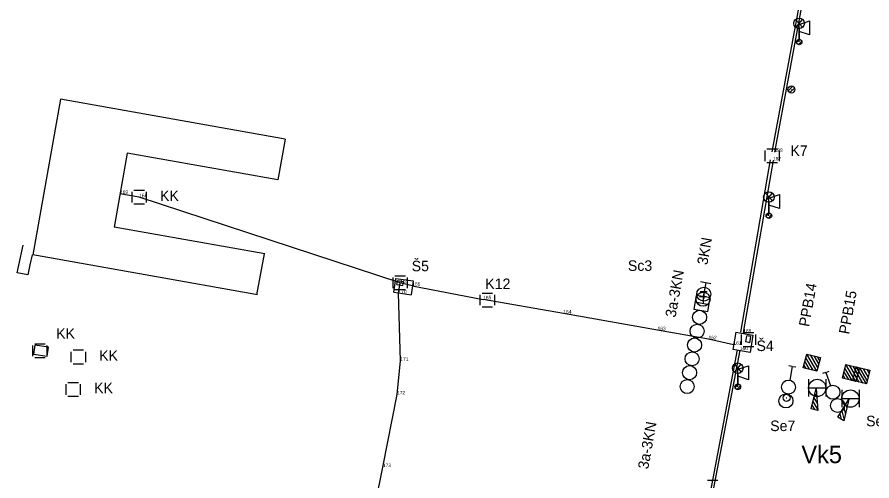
# Model space of a CAD drawing. Extents: x -866945 to -849632, y -1066564 to -1049105.
# Drawn here: x -866577.7 to -866456.1, y -1049962.8 to -1049896.8 of the extents above; entities that cross this region are included whole.
import ezdxf

# ---------------------------------------------------------------- set-up
doc = ezdxf.new("R2010")
doc.units = 0
for name, color, linetype in [('Vrstva 16', 7, 'Continuous'), ('Vrstva 2', 7, 'Continuous'), ('Vrstva 23', 7, 'Continuous'), ('Vrstva 25', 7, 'Continuous'), ('Vrstva 3', 7, 'Continuous'), ('Vrstva 31', 7, 'Continuous'), ('Vrstva 32', 7, 'Continuous'), ('Vrstva 33', 7, 'Continuous'), ('Vrstva 35', 7, 'Continuous'), ('Vrstva 36', 7, 'Continuous'), ('Vrstva 51', 7, 'Continuous'), ('Vrstva 52', 7, 'Continuous'), ('Vrstva 6', 7, 'Continuous'), ('Vrstva 7', 7, 'Continuous')]:
    doc.layers.add(name, color=color, linetype=linetype)

msp = doc.modelspace()

# ---------------------------------------------------------------- linework, layer by layer
at = {"layer": 'Vrstva 16'}
for p, q in [((-866524.06, -1049935.92), (-866523.79, -1049933.97)), ((-866523.79, -1049933.97), (-866521.33, -1049934.31)), ((-866523.66, -1049934.83), (-866523.57, -1049934.24)), ((-866523.57, -1049934.24), (-866522.69, -1049934.37)), ((-866523.66, -1049934.83), (-866522.78, -1049934.97)), ((-866522.78, -1049934.97), (-866522.69, -1049934.37)), ((-866521.33, -1049934.31), (-866521.6, -1049936.28)), ((-866524.06, -1049935.91), (-866524.06, -1049935.92)), ((-866524.06, -1049935.91), (-866521.6, -1049936.28)), ((-866475.44, -1049941.61), (-866475.86, -1049944.06)), ((-866475.44, -1049941.61), (-866472.99, -1049942.02)), ((-866474.02, -1049943), (-866473.87, -1049942.12)), ((-866473.28, -1049942.23), (-866473.87, -1049942.12)), ((-866473.43, -1049943.11), (-866473.28, -1049942.23)), ((-866472.99, -1049942.02), (-866473.4, -1049944.49)), ((-866473.43, -1049943.11), (-866474.02, -1049943)), ((-866473.4, -1049944.49), (-866475.86, -1049944.06))]:
    msp.add_line(p, q, dxfattribs=at)
at = {"layer": 'Vrstva 23'}
for points in [[(-866571.49, -1049908.45), (-866575.43, -1049930.6)], [(-866539.52, -1049914.14), (-866571.49, -1049908.45)], [(-866539.52, -1049914.14), (-866540.55, -1049919.93)], [(-866561.99, -1049916.12), (-866563.86, -1049926.65)], [(-866540.55, -1049919.93), (-866561.99, -1049916.12)], [(-866542.42, -1049930.46), (-866563.86, -1049926.65)], [(-866543.46, -1049936.29), (-866575.43, -1049930.6)], [(-866542.5, -1049930.45), (-866543.58, -1049936.27)]]:
    msp.add_lwpolyline(points, dxfattribs=at)
at = {"layer": 'Vrstva 25'}
for p, q in [((-866466.92, -1049897.09), (-866465.93, -1049898.21)), ((-866466.91, -1049898.22), (-866465.93, -1049897.1)), ((-866466.43, -1049898.4), (-866466.43, -1049899.9)), ((-866466.82, -1049900.38), (-866466.35, -1049899.91)), ((-866466.55, -1049900.68), (-866466.05, -1049900.18)), ((-866471.22, -1049921.81), (-866470.23, -1049922.93)), ((-866471.21, -1049922.94), (-866470.22, -1049921.82)), ((-866470.73, -1049923.12), (-866470.73, -1049924.62)), ((-866471.12, -1049925.1), (-866470.65, -1049924.63)), ((-866470.85, -1049925.4), (-866470.35, -1049924.9)), ((-866475.64, -1049946.17), (-866474.65, -1049947.28)), ((-866475.63, -1049947.3), (-866474.65, -1049946.18)), ((-866475.15, -1049947.48), (-866475.15, -1049948.98)), ((-866475.54, -1049949.46), (-866475.07, -1049948.99)), ((-866475.27, -1049949.76), (-866474.77, -1049949.26))]:
    msp.add_line(p, q, dxfattribs=at)
for centre, radius in [((-866466.43, -1049897.65), 0.749), ((-866466.43, -1049900.3), 0.4), ((-866466.43, -1049900.3), 0.4), ((-866470.73, -1049922.37), 0.749), ((-866470.73, -1049925.02), 0.4), ((-866470.73, -1049925.02), 0.4), ((-866475.15, -1049946.73), 0.749), ((-866475.15, -1049949.38), 0.4), ((-866475.15, -1049949.38), 0.4)]:
    msp.add_circle(centre, radius, dxfattribs=at)
at = {"layer": 'Vrstva 3'}
for p, q in [((-866480.59, -1049936.51), (-866479.59, -1049936.51)), ((-866480.49, -1049935.79), (-866479.49, -1049935.79)), ((-866480.09, -1049936.51), (-866480.09, -1049937.51)), ((-866479.99, -1049935.79), (-866479.99, -1049936.79)), ((-866464.42, -1049947.03), (-866465.47, -1049945.24)), ((-866463.9, -1049947.16), (-866465.34, -1049944.72)), ((-866463.77, -1049946.65), (-866464.83, -1049944.85)), ((-866463.64, -1049946.13), (-866464.31, -1049944.99)), ((-866463.51, -1049945.62), (-866463.8, -1049945.12)), ((-866465.44, -1049946.76), (-866465.74, -1049946.26)), ((-866464.93, -1049946.89), (-866465.61, -1049945.75)), ((-866458.34, -1049948.63), (-866459.78, -1049946.19)), ((-866458.21, -1049948.12), (-866459.27, -1049946.32)), ((-866459.37, -1049948.36), (-866460.05, -1049947.22)), ((-866458.86, -1049948.5), (-866459.91, -1049946.71)), ((-866458.08, -1049947.6), (-866458.75, -1049946.46)), ((-866457.89, -1049948.7), (-866458.57, -1049947.56)), ((-866457.38, -1049948.84), (-866458.43, -1049947.05)), ((-866456.86, -1049948.97), (-866458.3, -1049946.53)), ((-866457.95, -1049947.09), (-866458.24, -1049946.59)), ((-866456.73, -1049948.46), (-866457.79, -1049946.66)), ((-866456.6, -1049947.94), (-866457.27, -1049946.8)), ((-866456.47, -1049947.43), (-866456.76, -1049946.93)), ((-866465.09, -1049948.31), (-866465.09, -1049950.77)), ((-866462.63, -1049948.31), (-866462.63, -1049950.77)), ((-866459.88, -1049948.23), (-866460.18, -1049947.73)), ((-866458.4, -1049948.57), (-866458.7, -1049948.07)), ((-866465.09, -1049949.54), (-866462.63, -1049949.54)), ((-866464.06, -1049949.93), (-866463.94, -1049950.14)), ((-866460.36, -1049949.82), (-866460.36, -1049952.28)), ((-866457.9, -1049949.82), (-866457.9, -1049952.28)), ((-866464.33, -1049950.95), (-866463.83, -1049951.81)), ((-866464.2, -1049950.44), (-866463.88, -1049950.97)), ((-866460.36, -1049951.05), (-866457.9, -1049951.05)), ((-866464.73, -1049952.49), (-866464.72, -1049952.51)), ((-866464.6, -1049951.98), (-866464.21, -1049952.64)), ((-866464.46, -1049951.47), (-866463.77, -1049952.64)), ((-866460.08, -1049952.34), (-866459.85, -1049953.3)), ((-866459.8, -1049951.89), (-866459.66, -1049952.49)), ((-866459.52, -1049951.44), (-866459.46, -1049951.67)), ((-866460.91, -1049953.69), (-866460.91, -1049953.71)), ((-866460.64, -1049953.24), (-866460.46, -1049953.99)), ((-866460.36, -1049952.79), (-866460.04, -1049954.12))]:
    msp.add_line(p, q, dxfattribs=at)
for points in [[(-866465.84, -1049946.66), (-866465.34, -1049944.72), (-866463.4, -1049945.22), (-866463.9, -1049947.16)], [(-866465.84, -1049946.66), (-866465.34, -1049944.72), (-866463.4, -1049945.22), (-866463.9, -1049947.16)], [(-866460.28, -1049948.13), (-866459.78, -1049946.19), (-866457.84, -1049946.69), (-866458.34, -1049948.63)], [(-866460.28, -1049948.13), (-866459.78, -1049946.19), (-866457.84, -1049946.69), (-866458.34, -1049948.63)], [(-866458.8, -1049948.47), (-866458.3, -1049946.53), (-866456.36, -1049947.03), (-866456.86, -1049948.97)], [(-866458.8, -1049948.47), (-866458.3, -1049946.53), (-866456.36, -1049947.03), (-866456.86, -1049948.97)]]:
    msp.add_lwpolyline(points, close=True, dxfattribs=at)
for points in [[(-866465.84, -1049946.66), (-866465.34, -1049944.72), (-866463.4, -1049945.22), (-866463.9, -1049947.16), (-866465.84, -1049946.66)], [(-866465.84, -1049946.66), (-866465.34, -1049944.72), (-866463.4, -1049945.22), (-866463.9, -1049947.16), (-866465.84, -1049946.66)], [(-866460.28, -1049948.13), (-866459.78, -1049946.19), (-866457.84, -1049946.69), (-866458.34, -1049948.63), (-866460.28, -1049948.13)], [(-866460.28, -1049948.13), (-866459.78, -1049946.19), (-866457.84, -1049946.69), (-866458.34, -1049948.63), (-866460.28, -1049948.13)], [(-866458.8, -1049948.47), (-866458.3, -1049946.53), (-866456.36, -1049947.03), (-866456.86, -1049948.97), (-866458.8, -1049948.47)], [(-866458.8, -1049948.47), (-866458.3, -1049946.53), (-866456.36, -1049947.03), (-866456.86, -1049948.97), (-866458.8, -1049948.47)], [(-866463.98, -1049949.6), (-866463.77, -1049952.76), (-866464.73, -1049952.5), (-866463.98, -1049949.6)], [(-866463.98, -1049949.6), (-866463.77, -1049952.76), (-866464.73, -1049952.5), (-866463.98, -1049949.6)], [(-866459.34, -1049951.15), (-866460.07, -1049954.23), (-866460.92, -1049953.7), (-866459.34, -1049951.15)], [(-866459.34, -1049951.15), (-866460.07, -1049954.23), (-866460.92, -1049953.7), (-866459.34, -1049951.15)]]:
    msp.add_lwpolyline(points, dxfattribs=at)
for centre, radius in [((-866479.99, -1049936.19), 1), ((-866480.09, -1049936.91), 1), ((-866463.86, -1049949.54), 1.23), ((-866459.13, -1049951.05), 1.23)]:
    msp.add_circle(centre, radius, dxfattribs=at)
at = {"layer": 'Vrstva 32'}
msp.add_line((-866475.76, -1049943.41), (-866479.31, -1049942.62), dxfattribs=at)
for points in [[(-866467.53, -1049907.06), (-866467.46, -1049907.09)], [(-866521.45, -1049935), (-866523.16, -1049934.59), (-866560.29, -1049922.4), (-866563.02, -1049921.91)], [(-866546.33, -1050037.54), (-866545.05, -1050037.8), (-866543.62, -1050037.78), (-866542.32, -1050036.4), (-866541.04, -1050031.45), (-866538.21, -1050019.09), (-866535.65, -1050003.43), (-866534.99, -1050000.66), (-866533.44, -1049996.5), (-866532.34, -1049992.41), (-866530.9, -1049985.87), (-866527.79, -1049971.38), (-866525.62, -1049960.81), (-866523.61, -1049950.46), (-866523.14, -1049945.69), (-866523.41, -1049936.07), (-866523.16, -1049934.59)], [(-866479.31, -1049942.62), (-866486.56, -1049941.33), (-866499.96, -1049938.96), (-866511.37, -1049936.93)]]:
    msp.add_lwpolyline(points, dxfattribs=at)
at = {"layer": 'Vrstva 33'}
for p, q in [((-866466.43, -1049900.3), (-866466.43, -1049897.5)), ((-866470.73, -1049925.02), (-866470.73, -1049922.22)), ((-866475.15, -1049949.38), (-866475.15, -1049946.58))]:
    msp.add_line(p, q, dxfattribs=at)
for points in [[(-866466.43, -1049897.8), (-866464.93, -1049897.3), (-866464.93, -1049899.3), (-866466.43, -1049898.8)], [(-866470.73, -1049922.52), (-866469.23, -1049922.02), (-866469.23, -1049924.02), (-866470.73, -1049923.52)], [(-866475.15, -1049946.88), (-866473.65, -1049946.38), (-866473.65, -1049948.38), (-866475.15, -1049947.88)]]:
    msp.add_lwpolyline(points, dxfattribs=at)
at = {"layer": 'Vrstva 35'}
for p, q in [((-866465.74, -1049891.34), (-866470.29, -1049915.91)), ((-866465.37, -1049891.2), (-866469.92, -1049915.96)), ((-866471.26, -1049917.25), (-866471.26, -1049915.75)), ((-866471.01, -1049915.5), (-866469.51, -1049915.5)), ((-866469.26, -1049915.75), (-866469.26, -1049917.25)), ((-866470.54, -1049917.07), (-866474.75, -1049941.59)), ((-866470.13, -1049917.16), (-866474.38, -1049941.66)), ((-866469.51, -1049917.5), (-866471.01, -1049917.5)), ((-866561.29, -1049923.15), (-866561.29, -1049921.65)), ((-866561.04, -1049921.4), (-866559.54, -1049921.4)), ((-866559.29, -1049921.65), (-866559.29, -1049923.15)), ((-866559.54, -1049923.4), (-866561.04, -1049923.4)), ((-866524.16, -1049935.34), (-866524.16, -1049933.84)), ((-866523.91, -1049933.59), (-866522.41, -1049933.59)), ((-866522.16, -1049933.84), (-866522.16, -1049935.34)), ((-866521.45, -1049935), (-866511.37, -1049936.93)), ((-866522.41, -1049935.59), (-866523.91, -1049935.59)), ((-866511.77, -1049937.78), (-866511.77, -1049936.28)), ((-866511.52, -1049936.03), (-866510.02, -1049936.03)), ((-866509.77, -1049936.28), (-866509.77, -1049937.78)), ((-866510.02, -1049938.03), (-866511.52, -1049938.03)), ((-866475.76, -1049943.41), (-866479.31, -1049942.62)), ((-866474.63, -1049943.42), (-866474.63, -1049941.92)), ((-866474.38, -1049941.67), (-866472.88, -1049941.67)), ((-866472.63, -1049941.92), (-866472.63, -1049943.42)), ((-866575.4, -1049945.01), (-866575.4, -1049943.51)), ((-866575.15, -1049943.26), (-866573.65, -1049943.26)), ((-866573.4, -1049943.51), (-866573.4, -1049945.01)), ((-866472.88, -1049943.67), (-866474.38, -1049943.67)), ((-866569.94, -1049945.89), (-866569.94, -1049944.39)), ((-866569.69, -1049944.14), (-866568.19, -1049944.14)), ((-866567.94, -1049944.39), (-866567.94, -1049945.89)), ((-866475.23, -1049944.1), (-866479.04, -1049964.21)), ((-866474.86, -1049944.15), (-866478.69, -1049964.26)), ((-866573.65, -1049945.26), (-866575.15, -1049945.26)), ((-866568.19, -1049946.14), (-866569.69, -1049946.14)), ((-866570.42, -1049948.75), (-866568.92, -1049948.75)), ((-866570.67, -1049950.5), (-866570.67, -1049949)), ((-866568.67, -1049949), (-866568.67, -1049950.5)), ((-866568.92, -1049950.75), (-866570.42, -1049950.75)), ((-866479.48, -1049962.69), (-866477.98, -1049962.69))]:
    msp.add_line(p, q, dxfattribs=at)
msp.add_lwpolyline([(-866479.31, -1049942.62), (-866486.56, -1049941.33), (-866499.96, -1049938.96), (-866511.37, -1049936.93)], dxfattribs=at)
at = {"layer": 'Vrstva 36'}
for p, q in [((-866467.99, -1049907.24), (-866467.34, -1049906.6)), ((-866467.73, -1049907.51), (-866467.08, -1049906.86))]:
    msp.add_line(p, q, dxfattribs=at)
msp.add_circle((-866467.53, -1049907.06), 0.5, dxfattribs=at)
at = {"layer": 'Vrstva 51'}
for points in [[(-866575.51, -1049930.59), (-866575.82, -1049932.01), (-866576.13, -1049933.42), (-866577.65, -1049933.17), (-866577.41, -1049932.05), (-866576.8, -1049929.22)], [(-866575.34, -1049944.73), (-866573.37, -1049945.03), (-866573.17, -1049943.75), (-866575.11, -1049943.45), (-866575.34, -1049944.73)]]:
    msp.add_lwpolyline(points, dxfattribs=at)
at = {"layer": 'Vrstva 6'}
for p, q in [((-866478.97, -1049934.7), (-866480.45, -1049934.44)), ((-866479.71, -1049934.57), (-866479.71, -1049934.57)), ((-866479.25, -1049937.7), (-866481.22, -1049937.35)), ((-866467.4, -1049946.47), (-866467.89, -1049946.38)), ((-866467.4, -1049946.47), (-866467.76, -1049948.44)), ((-866467.4, -1049946.47), (-866466.91, -1049946.56)), ((-866462.62, -1049947.32), (-866463.09, -1049947.49)), ((-866462.62, -1049947.32), (-866462.15, -1049947.15)), ((-866462.62, -1049947.32), (-866461.95, -1049949.21))]:
    msp.add_line(p, q, dxfattribs=at)
msp.add_lwpolyline([(-866479.71, -1049934.57), (-866480.06, -1049936.54), (-866481.05, -1049936.36), (-866481.4, -1049938.33), (-866479.43, -1049938.68), (-866479.08, -1049936.71), (-866480.06, -1049936.54)], dxfattribs=at)
for centre in [(-866480.59, -1049939.49), (-866480.94, -1049941.46), (-866481.3, -1049943.43), (-866481.65, -1049945.4), (-866482, -1049947.37), (-866482.35, -1049949.34), (-866467.94, -1049949.42), (-866461.62, -1049950.15), (-866468.3, -1049951.39), (-866460.96, -1049952.04)]:
    msp.add_circle(centre, 1, dxfattribs=at)
at = {"layer": 'Vrstva 7'}
msp.add_line((-866468.26, -1049950.95), (-866468.16, -1049950.95), dxfattribs=at)
msp.add_circle((-866468.21, -1049950.95), 0.5, dxfattribs=at)

# ---------------------------------------------------------------- texts
at = {"layer": 'Vrstva 2'}
msp.add_text('Vk5', height=2.5, dxfattribs=at).set_placement((-866466.1, -1049960.25))
at = {"layer": 'Vrstva 3'}
for s, rotation, p in [('3KN', 79.8208, (-866479.49, -1049932.11)), ('3a-3KN', 79.8028, (-866484.01, -1049939.58)), ('PPB14', 79.8304, (-866465.01, -1049940.91)), ('PPB15', 79.8304, (-866459.32, -1049941.98)), ('3a-3KN', 79.8129, (-866487.9, -1049961.18))]:
    msp.add_text(s, height=1.5, rotation=rotation, dxfattribs=at).set_placement(p)
at = {"layer": 'Vrstva 31'}
for s, p in [('K7', (-866467.67, -1049916.52)), ('Š5', (-866521.53, -1049932.93)), ('K12', (-866511.06, -1049935.47)), ('Š4', (-866472.49, -1049944.29))]:
    msp.add_text(s, height=1.5, dxfattribs=at).set_placement(p)
at = {"layer": 'Vrstva 35'}
for p in [(-866557.32, -1049922.94), (-866572.08, -1049942.54), (-866565.97, -1049945.68), (-866566.7, -1049950.29)]:
    msp.add_text('KK', height=1.5, dxfattribs=at).set_placement(p)
at = {"layer": 'Vrstva 52'}
for s, p in [('188', (-866469.92, -1049915.96)), ('187', (-866470.13, -1049917.16)), ('169', (-866563.02, -1049921.91)), ('168', (-866560.29, -1049922.4)), ('167', (-866523.16, -1049934.59)), ('166', (-866521.45, -1049935)), ('170', (-866523.41, -1049936.07)), ('165', (-866511.37, -1049936.93)), ('164', (-866499.96, -1049938.96)), ('163', (-866486.56, -1049941.33)), ('186', (-866474.38, -1049941.66)), ('162', (-866479.31, -1049942.62)), ('161', (-866475.76, -1049943.41)), ('160', (-866474.86, -1049944.15)), ('171', (-866523.14, -1049945.69)), ('172', (-866523.61, -1049950.46)), ('173', (-866525.62, -1049960.81))]:
    msp.add_text(s, height=0.5, dxfattribs=at).set_placement(p)
at = {"layer": 'Vrstva 6'}
for s, p in [('Sc3', (-866490.78, -1049932.88)), ('Se8', (-866456.9, -1049955)), ('Se7', (-866470.54, -1049955.68))]:
    msp.add_text(s, height=1.5, dxfattribs=at).set_placement(p)

doc.saveas('drawing.dxf')
